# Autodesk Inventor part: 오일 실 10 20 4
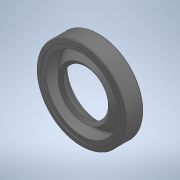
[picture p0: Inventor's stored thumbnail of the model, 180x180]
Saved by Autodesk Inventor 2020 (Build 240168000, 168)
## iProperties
Created: 2024-05
Part Number: 오일 실 10 20 4
Material: 고무
Description: 오일 실 - 비스프링, 조립 GA
Document SubType Name: Modeling
Designer: oem
Density: 0.93 g/cm^3
Appearance: 기본값
Author: jhkim
Sending System: Autodesk Inventor 2025
Preprocessor: ST-DEVELOPER v20
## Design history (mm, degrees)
node "오일 실 10 20 41"
node "솔리드1"
body "Solid1"
